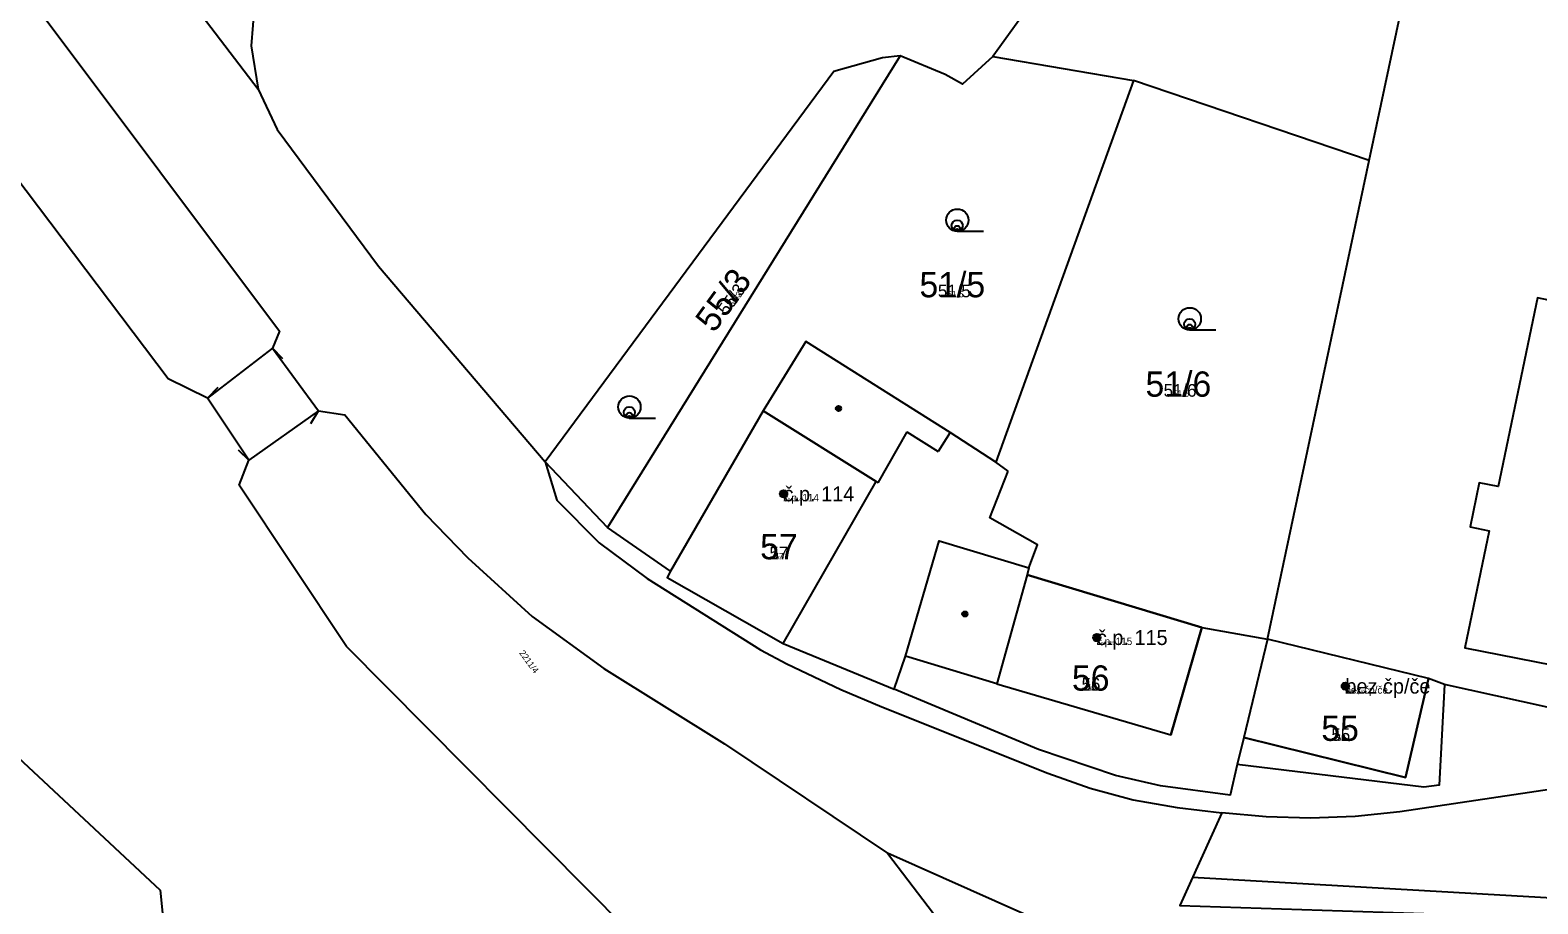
# Model space of a CAD drawing. Extents: x -744652 to -739090, y -980828 to -975855.
# Drawn here: x -742814.4 to -742712.9, y -978620.9 to -978562.2 of the extents above; entities that cross this region are included whole.
import ezdxf

# ---------------------------------------------------------------- set-up
doc = ezdxf.new("R2010")
doc.units = 0
for name, color, linetype in [('KAT_02_hranice parcel', 7, 'Continuous'), ('KAT_03_1000_st čísla parcelní', 7, 'Continuous'), ('KAT_03_1000_čísla parcelní', 7, 'Continuous'), ('KAT_03_1000_čísla popisná', 7, 'Continuous'), ('KAT_03_100_st čísla parcelní', 7, 'Continuous'), ('KAT_03_100_čísla parcelní', 7, 'Continuous'), ('KAT_03_100_čísla popisná', 7, 'Continuous'), ('KAT_03_250_st čísla parcelní', 7, 'Continuous'), ('KAT_03_250_čísla parcelní', 7, 'Continuous'), ('KAT_03_250_čísla popisná', 7, 'Continuous'), ('KAT_03_500_st čísla parcelní', 7, 'Continuous'), ('KAT_03_500_čísla parcelní', 7, 'Continuous'), ('KAT_03_500_čísla popisná', 7, 'Continuous'), ('KAT_04_vnitřní kresba', 7, 'Continuous'), ('KAT_05_1000_značky kultur', 7, 'Continuous'), ('KAT_05_100_značky kultur', 7, 'Continuous'), ('KAT_05_250_značky kultur', 7, 'Continuous'), ('KAT_05_500_značky kultur', 7, 'Continuous'), ('KAT_07_1000_značky budov', 7, 'Continuous'), ('KAT_07_100_značky budov', 7, 'Continuous'), ('KAT_07_500_značky budov', 7, 'Continuous'), ('KAT_10_věcná břemena', 7, 'Continuous'), ('KAT_14_plocha_budovy', 7, 'Continuous')]:
    doc.layers.add(name, color=color, linetype=linetype)

msp = doc.modelspace()

# ---------------------------------------------------------------- linework, layer by layer
at = {"layer": 'KAT_02_hranice parcel'}
for p, q in [((-742724.27, -978570.92), (-742720.83, -978554.79)), ((-742806.87, -978555.83), (-742799.02, -978566.13)), ((-742755.83, -978563.88), (-742775.51, -978595.62)), ((-742749.6, -978563.92), (-742740.12, -978565.55)), ((-742740.12, -978565.55), (-742749.39, -978591.22)), ((-742724.27, -978570.92), (-742740.12, -978565.55)), ((-742731.1, -978603.14), (-742724.27, -978570.92)), ((-742775.51, -978595.62), (-742779.71, -978591.21)), ((-742748.55, -978591.82), (-742749.39, -978591.22)), ((-742771.27, -978598.55), (-742775.51, -978595.62)), ((-742734.19, -978614.83), (-742737.02, -978621.05)), ((-742743.34, -978623.47), (-742756.67, -978617.54))]:
    msp.add_line(p, q, dxfattribs=at)
for points in [[(-742771.68, -978622.59), (-742774.27, -978622.61), (-742793.09, -978603.62), (-742800.31, -978592.77), (-742799.65, -978591.08), (-742802.44, -978586.91), (-742805.09, -978585.62), (-742832.93, -978548.75), (-742875.96, -978495.73), (-742875.72, -978493.96), (-742876.21, -978494.33), (-742877.8, -978492.59), (-742877.23, -978491.96), (-742922.49, -978451.07), (-742930.46, -978446.01), (-742968.31, -978424.94), (-743001.01, -978402.7), (-743006.74, -978399.94), (-743010.2, -978401.12)], [(-742944.36, -978423.99), (-742890.98, -978469.87), (-742872.41, -978486.88), (-742871.83, -978486.28), (-742870.13, -978487.96), (-742870.53, -978488.4), (-742857.69, -978502.54), (-742821.76, -978550.15), (-742797.59, -978582.4), (-742798.06, -978583.56), (-742794.96, -978587.77), (-742793.2, -978588.05), (-742787.74, -978594.75), (-742784.91, -978597.67), (-742780.59, -978601.61), (-742775.76, -978605.1), (-742767.64, -978610.17), (-742756.67, -978617.54)], [(-742714.32, -978532.88), (-742725.01, -978529.87), (-742749.6, -978563.92)], [(-742791.78, -978540.53), (-742799.28, -978560.43), (-742799.5, -978563.22), (-742799.02, -978566.13)], [(-742755.83, -978563.88), (-742757.01, -978564.02), (-742760.28, -978564.93), (-742779.71, -978591.21)], [(-742749.6, -978563.92), (-742751.63, -978565.78), (-742752.8, -978565.13), (-742755.83, -978563.88)], [(-742799.02, -978566.13), (-742797.74, -978568.85), (-742790.93, -978578.04), (-742779.71, -978591.21)], [(-742702.3, -978606.79), (-742698.7, -978589.67), (-742694.62, -978590.56), (-742690.81, -978573.96), (-742701.87, -978571.32), (-742703.87, -978580.04), (-742703.61, -978582.14), (-742712.95, -978580.17), (-742715.59, -978592.86), (-742716.86, -978592.62), (-742717.48, -978595.58), (-742716.2, -978595.84), (-742717.84, -978603.72), (-742708.35, -978605.57)], [(-742749.39, -978591.22), (-742752.46, -978589.22), (-742762.18, -978583.11), (-742765.05, -978587.77), (-742771.27, -978598.55)], [(-742779.71, -978591.21), (-742778.92, -978593.79), (-742776.07, -978596.65), (-742772.86, -978599.06), (-742765.22, -978603.85), (-742763.45, -978604.79), (-742759.82, -978606.52), (-742757.05, -978607.68), (-742745.88, -978612.15), (-742743.05, -978613.17), (-742740.16, -978613.95), (-742737.19, -978614.46), (-742734.19, -978614.83)], [(-742747.17, -978598.34), (-742746.59, -978596.79), (-742749.8, -978594.97), (-742748.55, -978591.82)], [(-742756.22, -978606.5), (-742755.46, -978604.27), (-742753.2, -978596.52), (-742747.17, -978598.34)], [(-742771.27, -978598.55), (-742771.51, -978598.98), (-742763.7, -978603.43), (-742756.22, -978606.5)], [(-742747.17, -978598.34), (-742747.28, -978598.81), (-742735.53, -978602.34), (-742731.1, -978603.14)], [(-742731.1, -978603.14), (-742732.71, -978609.75), (-742733.16, -978611.58)], [(-742719.2, -978606.19), (-742720.28, -978605.78), (-742731.1, -978603.14)], [(-742708.35, -978605.57), (-742708.85, -978608.48), (-742719.2, -978606.19)], [(-742733.16, -978611.58), (-742733.62, -978613.63), (-742738.3, -978613.01), (-742741.33, -978612.31), (-742746.51, -978610.56), (-742756.22, -978606.5)], [(-742719.2, -978606.19), (-742719.56, -978612.95), (-742720.59, -978613.09), (-742733.16, -978611.58)], [(-742832.81, -978621.35), (-742816.2, -978610.13), (-742805.61, -978620.02), (-742804.17, -978634.55), (-742832.81, -978621.35)], [(-742522.65, -978636.07), (-742549.97, -978633.28), (-742570.9, -978630.86), (-742578.86, -978629.74), (-742582.72, -978630.81), (-742604.63, -978627.47), (-742606.59, -978627.11), (-742643.73, -978618.95), (-742648.55, -978617.06), (-742656.38, -978615.82), (-742687.27, -978612.16), (-742690.29, -978611.84), (-742693.32, -978611.73), (-742696.29, -978611.66), (-742699.31, -978611.74), (-742704.32, -978612.08), (-742722.21, -978614.75), (-742725.22, -978615.06), (-742728.22, -978615.18), (-742731.2, -978615.09), (-742734.19, -978614.83)], [(-742756.67, -978617.54), (-742752.58, -978622.93), (-742749.26, -978627.81), (-742746.13, -978634.52), (-742745.98, -978639.46)]]:
    msp.add_lwpolyline(points, dxfattribs=at)
at = {"layer": 'KAT_03_1000_čísla popisná'}
for centre in [(-742763.67, -978593.36), (-742763.67, -978593.36), (-742742.59, -978603.03), (-742742.59, -978603.03), (-742725.87, -978606.3), (-742725.87, -978606.3)]:
    msp.add_circle(centre, 0.25, dxfattribs=at)
at = {"layer": 'KAT_03_100_čísla popisná'}
for centre in [(-742763.67, -978593.36), (-742763.67, -978593.36), (-742742.59, -978603.03), (-742742.59, -978603.03), (-742725.87, -978606.3), (-742725.87, -978606.3)]:
    msp.add_circle(centre, 0.025, dxfattribs=at)
at = {"layer": 'KAT_03_250_čísla popisná'}
for centre in [(-742763.67, -978593.36), (-742763.67, -978593.36), (-742742.59, -978603.03), (-742742.59, -978603.03), (-742725.87, -978606.3), (-742725.87, -978606.3)]:
    msp.add_circle(centre, 0.0625, dxfattribs=at)
at = {"layer": 'KAT_03_500_čísla popisná'}
for centre in [(-742763.67, -978593.36), (-742763.67, -978593.36), (-742742.59, -978603.03), (-742742.59, -978603.03), (-742725.87, -978606.3), (-742725.87, -978606.3)]:
    msp.add_circle(centre, 0.125, dxfattribs=at)
at = {"layer": 'KAT_04_vnitřní kresba'}
for p, q in [((-742798.06, -978583.56), (-742802.44, -978586.91)), ((-742797.36, -978584.28), (-742798.06, -978583.56)), ((-742801.73, -978586.2), (-742802.44, -978586.91)), ((-742794.96, -978587.77), (-742799.65, -978591.08)), ((-742795.49, -978588.62), (-742794.96, -978587.77)), ((-742765.05, -978587.77), (-742757.45, -978592.53)), ((-742755.37, -978589.18), (-742757.32, -978592.61)), ((-742755.37, -978589.18), (-742753.27, -978590.5)), ((-742752.46, -978589.22), (-742753.27, -978590.5)), ((-742800.38, -978590.4), (-742799.65, -978591.08)), ((-742763.7, -978603.43), (-742757.45, -978592.53)), ((-742757.45, -978592.53), (-742757.32, -978592.61)), ((-742747.28, -978598.81), (-742749.33, -978606.14)), ((-742735.53, -978602.34), (-742737.62, -978609.57)), ((-742749.33, -978606.14), (-742755.46, -978604.27)), ((-742749.33, -978606.14), (-742737.62, -978609.57)), ((-742720.28, -978605.78), (-742721.83, -978612.45)), ((-742721.83, -978612.45), (-742732.71, -978609.75))]:
    msp.add_line(p, q, dxfattribs=at)
at = {"layer": 'KAT_05_1000_značky kultur'}
for p, q in [((-742751.98, -978575.69), (-742750.23, -978575.69)), ((-742736.34, -978582.33), (-742734.59, -978582.33)), ((-742774.04, -978588.26), (-742772.29, -978588.26))]:
    msp.add_line(p, q, dxfattribs=at)
for centre in [(-742751.98, -978574.94), (-742736.34, -978581.58), (-742774.04, -978587.51)]:
    msp.add_circle(centre, 0.75, dxfattribs=at)
at = {"layer": 'KAT_05_100_značky kultur'}
for p, q in [((-742751.99, -978575.69), (-742751.81, -978575.69)), ((-742736.35, -978582.33), (-742736.17, -978582.33)), ((-742774.05, -978588.26), (-742773.87, -978588.26))]:
    msp.add_line(p, q, dxfattribs=at)
for centre in [(-742751.99, -978575.61), (-742736.35, -978582.25), (-742774.05, -978588.18)]:
    msp.add_circle(centre, 0.075, dxfattribs=at)
at = {"layer": 'KAT_05_250_značky kultur'}
for p, q in [((-742751.99, -978575.69), (-742751.55, -978575.69)), ((-742736.35, -978582.33), (-742735.91, -978582.33)), ((-742774.05, -978588.26), (-742773.61, -978588.26))]:
    msp.add_line(p, q, dxfattribs=at)
for centre in [(-742751.99, -978575.5), (-742736.35, -978582.14), (-742774.05, -978588.07)]:
    msp.add_circle(centre, 0.187, dxfattribs=at)
at = {"layer": 'KAT_05_500_značky kultur'}
for p, q in [((-742751.99, -978575.69), (-742751.11, -978575.69)), ((-742736.35, -978582.33), (-742735.47, -978582.33)), ((-742774.05, -978588.26), (-742773.17, -978588.26))]:
    msp.add_line(p, q, dxfattribs=at)
for centre in [(-742751.99, -978575.31), (-742736.35, -978581.95), (-742774.05, -978587.88)]:
    msp.add_circle(centre, 0.375, dxfattribs=at)
at = {"layer": 'KAT_07_1000_značky budov'}
for centre in [(-742759.97, -978587.61), (-742763.68, -978593.36), (-742751.47, -978601.44), (-742742.6, -978603.03), (-742725.88, -978606.3)]:
    msp.add_circle(centre, 0.175, dxfattribs=at)
at = {"layer": 'KAT_07_100_značky budov'}
for centre in [(-742759.96, -978587.61), (-742763.67, -978593.36), (-742751.46, -978601.44), (-742742.59, -978603.03), (-742725.87, -978606.3)]:
    msp.add_circle(centre, 0.0175, dxfattribs=at)
at = {"layer": 'KAT_07_500_značky budov'}
for centre, radius in [((-742759.96, -978587.61), 0.0875), ((-742759.96, -978587.61), 0.0438), ((-742763.67, -978593.36), 0.0875), ((-742763.67, -978593.36), 0.0438), ((-742751.46, -978601.44), 0.0875), ((-742751.46, -978601.44), 0.0438), ((-742742.59, -978603.03), 0.0875), ((-742742.59, -978603.03), 0.0438), ((-742725.87, -978606.3), 0.0875), ((-742725.87, -978606.3), 0.0438)]:
    msp.add_circle(centre, radius, dxfattribs=at)
at = {"layer": 'KAT_10_věcná břemena'}
msp.add_lwpolyline([(-742612.55, -978632.12), (-742641.67, -978624.81), (-742669.08, -978620.92), (-742706.88, -978620.85), (-742736.16, -978619.17), (-742737.02, -978621.05), (-742706.92, -978622.05), (-742669.16, -978622.12), (-742641.91, -978625.99), (-742612.75, -978633.3)], dxfattribs=at)
at = {"layer": 'KAT_14_plocha_budovy'}
for points in [[(-742715.59, -978592.86), (-742716.86, -978592.62), (-742717.48, -978595.58), (-742716.2, -978595.84), (-742717.84, -978603.72), (-742708.35, -978605.57), (-742703.61, -978582.14), (-742712.95, -978580.17)], [(-742771.51, -978598.98), (-742763.7, -978603.43), (-742757.45, -978592.53), (-742765.05, -978587.77), (-742771.27, -978598.55)], [(-742747.28, -978598.81), (-742749.33, -978606.14), (-742737.62, -978609.57), (-742735.53, -978602.34)], [(-742732.71, -978609.75), (-742721.83, -978612.45), (-742720.28, -978605.78), (-742731.1, -978603.14)]]:
    msp.add_lwpolyline(points, close=True, dxfattribs=at)

# ---------------------------------------------------------------- texts
at = {"layer": 'KAT_03_1000_st čísla parcelní'}
for s, p in [('57', (-742765.25, -978597.76)), ('56', (-742744.27, -978606.6)), ('55', (-742727.49, -978609.98))]:
    msp.add_text(s, height=1.7, dxfattribs=at).set_placement(p)
at = {"layer": 'KAT_03_1000_čísla parcelní'}
msp.add_text('55/3', height=1.7, rotation=54, dxfattribs=at).set_placement((-742768.35, -978582.59))
for s, p in [('51/5', (-742754.53, -978580.13)), ('51/6', (-742739.32, -978586.82))]:
    msp.add_text(s, height=1.7, dxfattribs=at).set_placement(p)
at = {"layer": 'KAT_03_1000_čísla popisná'}
for s, height, p in [('č.p. 114', 1, (-742763.67, -978593.86)), ('57', 0.017, (-742763.99, -978597.76)), ('č.p. 115', 1, (-742742.59, -978603.53)), ('56', 0.017, (-742742.97, -978606.6)), ('bez čp/če', 1, (-742725.87, -978606.8)), ('55', 0.017, (-742726.15, -978609.98))]:
    msp.add_text(s, height=height, dxfattribs=at).set_placement(p)
at = {"layer": 'KAT_03_100_st čísla parcelní'}
for s, p in [('57', (-742764.11, -978597.76)), ('56', (-742743.09, -978606.6)), ('55', (-742726.27, -978609.98))]:
    msp.add_text(s, height=0.17, dxfattribs=at).set_placement(p)
at = {"layer": 'KAT_03_100_čísla parcelní'}
msp.add_text('55/3', height=0.17, rotation=54, dxfattribs=at).set_placement((-742766.8, -978580.46))
for s, p in [('51/5', (-742752.29, -978580.13)), ('51/6', (-742737.12, -978586.82))]:
    msp.add_text(s, height=0.17, dxfattribs=at).set_placement(p)
at = {"layer": 'KAT_03_100_čísla popisná'}
for s, height, p in [('č.p. 114', 0.1, (-742763.67, -978593.86)), ('57', 0.0017, (-742763.98, -978597.76)), ('č.p. 115', 0.1, (-742742.59, -978603.53)), ('56', 0.0017, (-742742.96, -978606.6)), ('bez čp/če', 0.1, (-742725.87, -978606.8)), ('55', 0.0017, (-742726.13, -978609.98))]:
    msp.add_text(s, height=height, dxfattribs=at).set_placement(p)
at = {"layer": 'KAT_03_250_st čísla parcelní'}
for s, p in [('57', (-742764.3, -978597.76)), ('56', (-742743.29, -978606.6)), ('55', (-742726.47, -978609.98))]:
    msp.add_text(s, height=0.425, dxfattribs=at).set_placement(p)
at = {"layer": 'KAT_03_250_čísla parcelní'}
for s, rotation, p in [('55/3', 54, (-742767.06, -978580.82)), ('2211/4', 306, (-742781.48, -978604.07))]:
    msp.add_text(s, height=0.425, rotation=rotation, dxfattribs=at).set_placement(p)
for s, p in [('51/5', (-742752.66, -978580.13)), ('51/6', (-742737.49, -978586.82))]:
    msp.add_text(s, height=0.425, dxfattribs=at).set_placement(p)
at = {"layer": 'KAT_03_250_čísla popisná'}
for s, height, p in [('č.p. 114', 0.25, (-742763.67, -978593.86)), ('57', 0.00425, (-742763.98, -978597.76)), ('č.p. 115', 0.25, (-742742.59, -978603.53)), ('56', 0.00425, (-742742.96, -978606.6)), ('bez čp/če', 0.25, (-742725.87, -978606.8)), ('55', 0.00425, (-742726.14, -978609.98))]:
    msp.add_text(s, height=height, dxfattribs=at).set_placement(p)
at = {"layer": 'KAT_03_500_st čísla parcelní'}
for s, p in [('57', (-742764.62, -978597.76)), ('56', (-742743.62, -978606.6)), ('55', (-742726.81, -978609.98))]:
    msp.add_text(s, height=0.85, dxfattribs=at).set_placement(p)
at = {"layer": 'KAT_03_500_čísla parcelní'}
msp.add_text('55/3', height=0.85, rotation=54, dxfattribs=at).set_placement((-742767.49, -978581.41))
for s, p in [('51/5', (-742753.29, -978580.13)), ('51/6', (-742738.1, -978586.82))]:
    msp.add_text(s, height=0.85, dxfattribs=at).set_placement(p)
at = {"layer": 'KAT_03_500_čísla popisná'}
for s, height, p in [('č.p. 114', 0.5, (-742763.67, -978593.86)), ('57', 0.0085, (-742763.99, -978597.76)), ('č.p. 115', 0.5, (-742742.59, -978603.53)), ('56', 0.0085, (-742742.97, -978606.6)), ('bez čp/če', 0.5, (-742725.87, -978606.8)), ('55', 0.0085, (-742726.14, -978609.98))]:
    msp.add_text(s, height=height, dxfattribs=at).set_placement(p)

doc.saveas('drawing.dxf')
